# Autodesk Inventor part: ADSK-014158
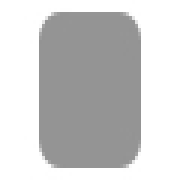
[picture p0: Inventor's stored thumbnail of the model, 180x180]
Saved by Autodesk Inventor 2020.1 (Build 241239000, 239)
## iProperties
Created: 2019-01
Part Number: ADSK-014158
Material: Stahl, weich
Document SubType Name: Modeling
Designer: lutzd
Language: de-DE
Size Designation: 5 x 39,384472 x 39,384472
Categories: <MemberInstance><Categories><Category DisplayName="Sonstige Bauteile" InternalName="5aa15e00-363f-49f2-933f-16f664388e3f" Mnemonic="OTHER"><Category DisplayName
Mass: 60.0398 g
Surface Area: 38.0412 cm^2
Volume: 7.64838 cm^3
Density: 7.85 g/cm^3
Appearance: Halbpoliert
Dimensions: 39,4x39,4x5 mm
Mass: 0,06 kg
DocNumber: ADSK-014158
Folder: 01 - Themengebiete\Simplification\01 - Packaging machine\
VDS_Category: 3D Komponenten
VDS_NumSchm: Autodesk
IsCustomPart: 1
Title: end cap
Author: lutzd
Revision Number: -
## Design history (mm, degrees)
sketch "Sketch1"
  geometry: L1 (0, 20.175)-(0, -21.446); L2 (-20.203, 0)-(20.169, 0); L3 (-19.692, 19.692)-(19.692, 19.692); L4 (19.692, 19.692)-(19.692, -19.692); L5 (19.692, -19.692)-(-19.692, -19.692); L6 (-19.692, -19.692)-(-19.692, 19.692); 1 further point
  constraints: 12 end point, 2 horizontal, 2 parallel, 2 point on line, 1 perpendicular, 1 vertical
  dimensions: "d0" = 39.38447 distance between parallel lines of L5 L3 (= height); "d1" = 19.69224 distance between parallel lines of L2 L3 (= 0.5 x height); "d2" = 39.38447 distance between parallel lines of L6 L4 (= width); "d3" = 19.69224 distance between parallel lines of L6 L1 (= 0.5 x width)
extrude "Extrusion1" new body sketch "Sketch1" distance "d4" = 5 (= thickness); taper "d5" = 0 deg
fillet "Fillet1" dims "d6" = 5 (= fillet), "d7" = 0, "fillet" = 5 [user parameter; used in 1 equation term]
chamfer "Chamfer1" distance "d8" = 0 (computed from chamfer); stored, may be unused: second distance "d9" = 2, angle "d10" = 45 deg; dims "d11" = 0, "chamfer" = 0 [user parameter; used in 1 equation term]
body "Solid1"
other parameters: "thickness" = 5 [user parameter; used in 1 equation term], "width" = 39.38447 [user parameter; used in 2 equation terms], "height" = 39.38447 [user parameter; used in 2 equation terms]
